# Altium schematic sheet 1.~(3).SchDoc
size 420 x 297 mm
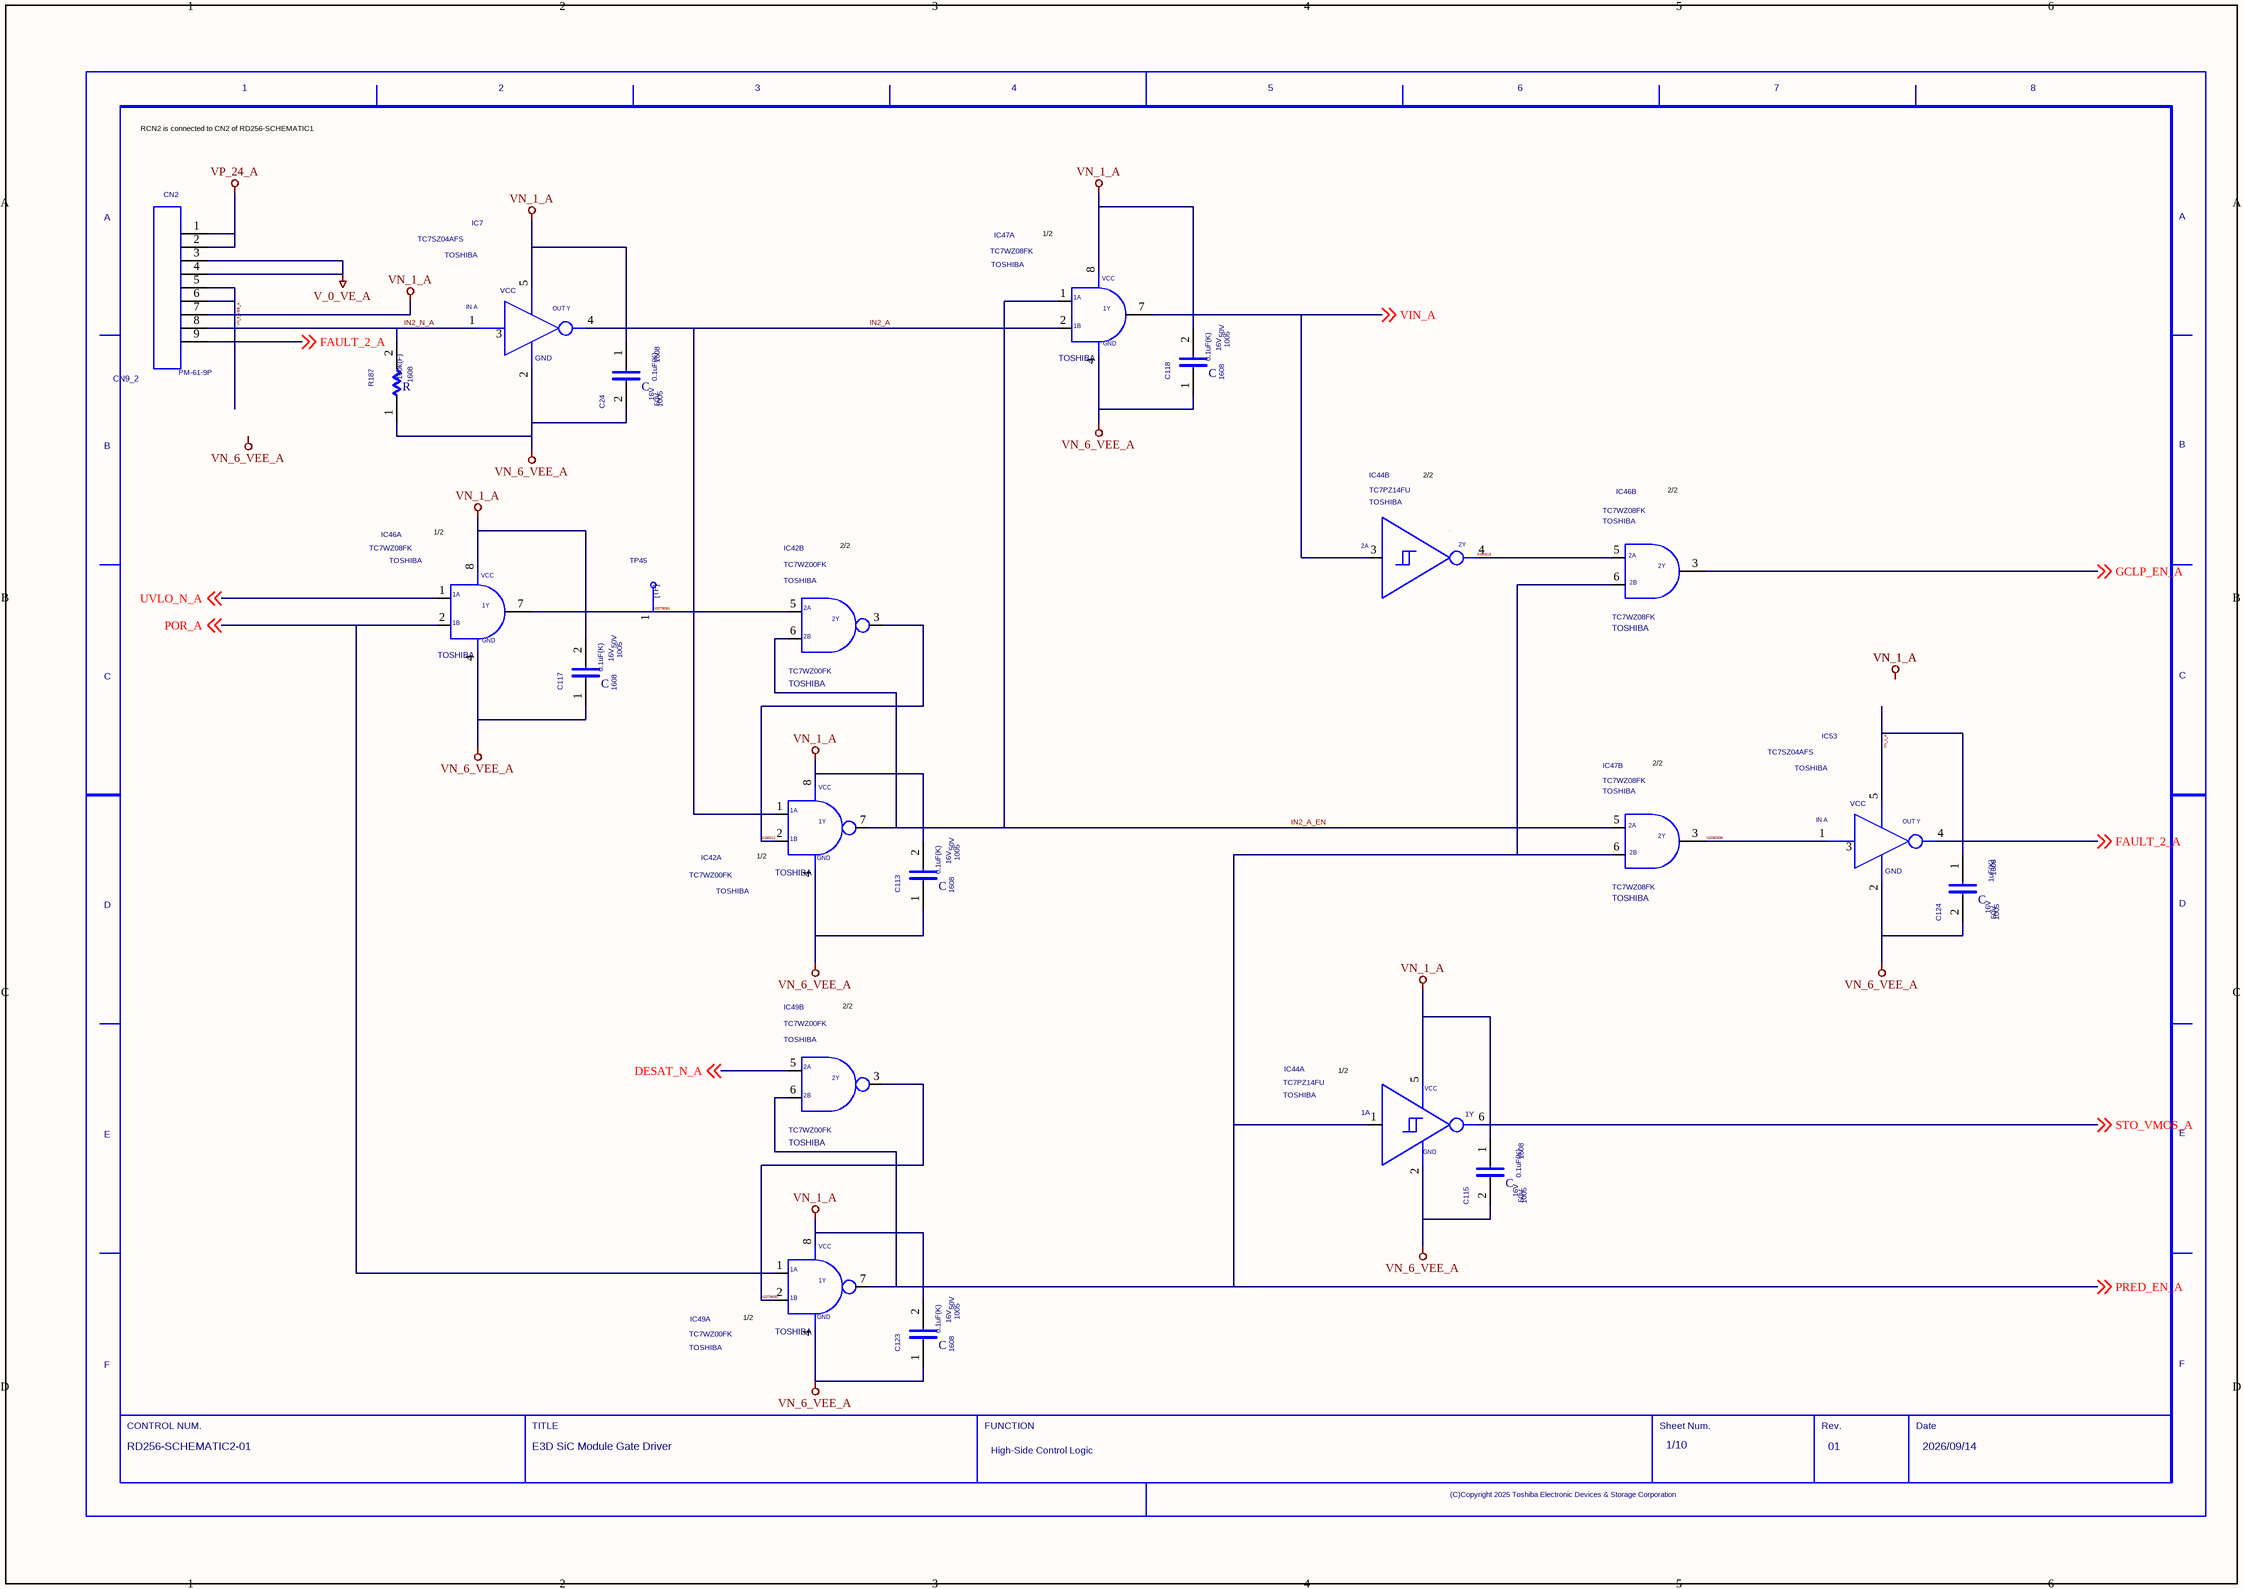
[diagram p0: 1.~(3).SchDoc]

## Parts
C24  VOLTAGE: 16V  CODE: 1005  VAL1: 0.1uF(K)  VAL2: 50V  SIZECODESMD: 1608  (hidden comment: C)
C113  VOLTAGE: 16V  CODE: 1005  VAL1: 0.1uF(K)  VAL2: 50V  SIZECODESMD: 1608  (hidden comment: C)
C115  VOLTAGE: 16V  CODE: 1005  VAL1: 0.1uF(K)  VAL2: 50V  SIZECODESMD: 1608  (hidden comment: C)
C117  VOLTAGE: 16V  CODE: 1005  VAL1: 0.1uF(K)  VAL2: 50V  SIZECODESMD: 1608  (hidden comment: C)
C118  VOLTAGE: 16V  CODE: 1005  VAL1: 0.1uF(K)  VAL2: 50V  SIZECODESMD: 1608  (hidden comment: C)
C123  VOLTAGE: 16V  CODE: 1005  VAL1: 0.1uF(K)  VAL2: 50V  SIZECODESMD: 1608  (hidden comment: C)
C124  VOLTAGE: 16V  CODE: 1005  VAL1: 1uF(K)  VAL2: 50V  SIZECODESMD: 1608  (hidden comment: C)
CN2  CN9_2  VAL3: PM-61-9P
IC7  USERCOMPTEXT3: TOSHIBA  (hidden comment: TC7SZ04AFS)
IC42  VENDOR: TOSHIBA  (hidden comment: TC7WZ00FK)  (parts A,B of 2)
IC44  VAL3: TC7PZ14FU  USERCOMPTEXT3: TOSHIBA  (hidden comment: TC7PZ17FU)  (parts A,B of 2)
IC46  VENDOR: TOSHIBA  (hidden comment: TC7WZ08FK)  (parts A,B of 2)
IC47  VENDOR: TOSHIBA  (hidden comment: TC7WZ08FK)  (parts A,B of 2)
IC49  VENDOR: TOSHIBA  (hidden comment: TC7WZ00FK)  (parts A,B of 2)
IC53  USERCOMPTEXT3: TOSHIBA  (hidden comment: TC7SZ04AFS)
R187  VAL1: 100k(F)  SIZECODESMD: 1608  (hidden comment: R)
TP45  TP  (value not drawn)
U?  REVISION: 01  SHEETNUMBER: 1/10  FUNCTION: High-Side Control Logic  TITLE: E3D SiC Module Gate Driver  DRAWINGNUMBER: RD256-SCHEMATIC2-01  DATE: 2026/09/14  (hidden comment: WAKU_DEF100)

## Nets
V_0_VE_A: CN2.3 CN2.4
VN_1_A: C24.1 C113.2 C115.1 C117.2 C118.2 C123.2 C124.1 CN2.7 IC7.5 IC42.8 IC44.5 IC46.8 IC47.8 IC49.8 IC53.5
VN_6_VEE_A: C24.2 C113.1 C115.2 C117.1 C118.1 C123.1 C124.2 CN2.5 CN2.6 IC7.2 IC42.4 IC44.2 IC46.4 IC47.4 IC49.4 IC53.2 R187.1
VP_24_A: CN2.1 CN2.2
DESAT_N_A: IC49.5(2A) ; off-sheet DESAT_N_A
FAULT_2_A: CN2.9 IC53.4 ; off-sheet FAULT_2_A
GCLP_EN_A: IC46.3 ; off-sheet GCLP_EN_A
IN2_A: IC7.4 IC42.1 IC47.2
IN2_A_EN: IC42.6(2B) IC42.7 IC47.1 IC47.5
IN2_N_A: CN2.8 IC7.1 R187.2
N2078081: IC42.5(2A) IC46.7 TP45.1
N2078630: IC49.2 IC49.3(2Y)
N2080336: IC47.3 IC53.1
POR_A: IC46.2 IC49.1 ; off-sheet POR_A
PRED_EN_A: IC44.1 IC46.6 IC47.6 IC49.6(2B) IC49.7 ; off-sheet PRED_EN_A
SIG0012: IC42.2 IC42.3(2Y)
SIG0013: IC44.4 IC46.5
STO_VMOS_A: IC44.6 ; off-sheet STO_VMOS_A
UVLO_N_A: IC46.1 ; off-sheet UVLO_N_A
VIN_A: IC44.3 IC47.7 ; off-sheet VIN_A

Not connected (* = marked no-connect by the designer): IC7 3; IC53 3

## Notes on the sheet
- RCN2 is connected to CN2 of RD256-SCHEMATIC1
- (near IC47) 1/2
- (near IC46) 1/2
- 2/2
- (near IC42) 1/2
- (near IC44) 1/2
- (near IC49) 1/2
- Labels drawn without touching a wire or pin: VN_6_VEE_A

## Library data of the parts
C24 C113 C115 C117 C118 C123 C124 = C: ORIGINALSYMBOLORIGIN: (0,0); VC2: 0; PSPICETEMPLATE: C^@REFDES %1 %2 ?TOLERANCE¦C^@REFDES¦ @VALUE ?IC/IC=@IC/ TC=@TC1,@TC2 ?TOLERANCE¦\n.model C^@REFDES CAP C=1 DEV=@TOLERANCE% TC1=@TC1 TC2=@TC2 VC1=@VC1 VC2=@VC2¦; SAVECOUNT: 2; UPDATETIME: 08:48:12; UPDATEUSER: HP_Z8_KEYSHOT; INSTANCENAME: INS2265204
CN2 = CN9_1: OriginalSymbolOrigin: (0,0); USER_VALUE: XG4A-1031; PSPICETEMPLATE: X^@REFDES %1 %2 %3 %4 %5 %6 %7 %8 %9 %10 %M1 %M2 @MODEL; SAVECOUNT: 2; UPDATETIME: 08:48:13; UPDATEUSER: HP_Z8_KEYSHOT; INSTANCENAME: INS2253568
IC7 IC53 = TC7SZ04AFS: OriginalSymbolOrigin: (0,-5080); PSPICETEMPLATE: X^@REFDES %INA %GND %NC %OUTY %VCC @MODEL; SAVECOUNT: 6; UPDATETIME: 19:30:29; UPDATEUSER: t5459927; TIME: 11:55:02; INSTANCENAME: INS2254048
IC42 IC49 = TC7WZ00FK_2: PART NUMBER: TC7W00FK; ORIGINALSYMBOLORIGIN: (2540,-2540); DESCRIPTION-A: NAND 2ch Logic; PSPICETEMPLATE: X^@REFDES %1A %1B %2Y %GND %2A %2B %1Y %VCC @MODEL; ・: 7 V; SPLIT_INST: TRUE; ORDER: $pOrder; SWAP_INFO: (S1+S2); SAVECOUNT: 5; UPDATETIME: 16:09:46; UPDATEUSER: sptcae09; TIME: 08:52:39; INSTANCENAME: INS2253652; FUNCN: TC7WZ00FK_1; CaptureCellPackProp: TC7WZ00FK_2A
IC44 = TC7PZ14FU_2: OriginalSymbolOrigin: (5080,15240); SWAP_INFO: (S1+S2); PSPICETEMPLATE: X^@REFDES %1A %GND %2A %2Y %VCC %1Y @MODEL; SPLIT_INST: TRUE; SAVECOUNT: 7; UPDATETIME: 19:09:34; UPDATEUSER: t5459927; TIME: 11:55:01; INSTANCENAME: INS2254016; FUNCN: TC7PZ14FU_1; CaptureCellPackProp: TC7PZ14FU_2A
IC46 IC47 = TC7WZ08FK_1: PART NUMBER: TC7W00FK; ORIGINALSYMBOLORIGIN: (2540,-2540); DESCRIPTION-A: NAND 2ch Logic; PSPICETEMPLATE: X^@REFDES %1A %1B %2Y %GND %2A %2B %1Y %VCC @MODEL; ・: 7 V; SPLIT_INST: TRUE; ORDER: $pOrder; SWAP_INFO: (S1+S2); SAVECOUNT: 5; UPDATETIME: 16:09:46; UPDATEUSER: sptcae09; TIME: 08:52:39; INSTANCENAME: INS2254084; CaptureCellPackProp: TC7WZ08FK_1A
R187 = R: ORIGINALSYMBOLORIGIN: (0,0); PSPICETEMPLATE: R^@REFDES %1 %2 ?TOLERANCE¦R^@REFDES¦ @VALUE TC=@TC1,@TC2 ?TOLERANCE¦\n.model R^@REFDES RES R=1 DEV=@TOLERANCE% TC1=@TC1 TC2=@TC2¦; TC2: 0; VAL2: 100mW; SAVECOUNT: 2; UPDATETIME: 08:48:13; UPDATEUSER: HP_Z8_KEYSHOT; INSTANCENAME: INS2263832
TP45 = TP: ORIGINALSYMBOLORIGIN: (0,0); SAVEAREA0: -242,-92,12810,7836; SAVECOUNT: 2; UPDATETIME: 16:18:11; UPDATEUSER: fukuda-y; TIME: 16:12:21; INSTANCENAME: INS2253720
U? = WAKU_DEF100: OriginalSymbolOrigin: (10160,284480); SAVECOUNT: 4; UPDATETIME: 12:22:00; UPDATEUSER: t5459927; TIME: 14:30:25; SAVEAREA0: -63393,-16950,474261,314592; PLOTTIME: HH:MM; SHTSAVECOUNT: 35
